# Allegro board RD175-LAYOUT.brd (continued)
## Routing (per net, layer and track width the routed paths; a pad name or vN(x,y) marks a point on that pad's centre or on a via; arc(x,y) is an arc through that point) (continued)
N552846: length 26.9
  TOP w0.7: v2(76.67,47.92) R71.1
  CONDUCTIVE3 w1: v2(76.67,47.92) 76.67,59.08 85.3,67.7 T5.10
N560018: length 3.2
  TOP w0.7: TP3.1 39.4,83.65
  BOTTOM w0.7: 39.1,83.35 R6.1
  BOTTOM w0.8: v2(39.12,83.35) 39.12,82.92
N560020: length 45.5
  TOP w0.6: 55.85,53.5 55.85,55.1 53.58,57.38 v1(47.5,57.38) ; v1(20.59,72.54) IC1.6 20.59,73.86
  CONDUCTIVE3 w0.6: v1(20.59,72.54) 20.59,72.39 35.6,57.38 v1(47.5,57.38)
N560028: length 2.2
  TOP w0.7: 33.75,47.2 Q1.1
N560032: length 7.4
  TOP w0.7: D6.2 76.9,44.2 76.67,43.98 C52.1 R72.2 82.47,43.2
N560040: length 3.8
  TOP w0.3: 88.58,50.2 R55.1 R56.2 ; IC3.8 88.62,50.2
N560044: length 52.7
  TOP w0.35: v2(98.45,52.62) 97.8,52.15 96.92,52.15
  CONDUCTIVE2 w1: v2(102.9,57.08) 103.85,58.02 103.85,71.3 104.25,71.7 104.25,80.75 103.9,81.1 103.9,84.8 101.65,87.05 v1(101.65,88.45) 101.65,89.45 103.62,91.42 v1(103.62,97.45)
  CONDUCTIVE3 w1: v2(98.45,52.62) v2(102.9,57.08)
  BOTTOM w0.7: v1(103.62,97.45) 102.72,97.45 ; R43.2 101.53,88.58 v1(101.65,88.45)
N560052: length 0.7
  TOP w0.6: 48.98,51.38 48.98,50.7
N560056: length 4.2
  CONDUCTIVE2 w0.6: v1(31.38,74.97) 31.38,73.95 TP6.1
  CONDUCTIVE3 w0.6: TP6.1 31.38,73.95 v1(31.38,74.97)
  BOTTOM w0.6: 31.43,73.92 31.38,73.97 v1(31.38,74.97) R13.1
N560060: length 4.2
  TOP w0.4: C121.2 49.65,21 50.1,21.45 50.52,21.45 ; C121.2 47.7,21 ; C121.2 48.98,19.85
N560066: length 25.4
  TOP w0.3: v1(89.92,49.5) 89.97,49.55 IC3.9 ; v1(78.55,37.67) R68.1
  CONDUCTIVE3 w0.3: v1(78.55,37.67) 86.8,37.67 89.92,40.8 v1(89.92,49.5)
N560076: length 1.2
  BOTTOM w0.7: v1(37.7,83.45) R6.2
N560080: length 31.9
  TOP w0.35: IC3.5 90.25,52.15 v2(89.58,52.67)
  CONDUCTIVE2 w0.6: v1(101.2,76.1) 101.1,76
  CONDUCTIVE2 w1: v2(98.03,61.12) 100.55,63.65 v1(100.55,66.38) 100.55,75.45 101.1,76
  BOTTOM w0.7: v1(101.2,76.1) R41.2 ; v1(100.55,66.38) R42.2
  BOTTOM w1: v2(98.03,61.12) v2(89.58,52.67)
N560082: length 2.7
  TOP w0.3: 96.92,53.45 96.92,53.48 97.64,53.48 97.96,53.8 R62.1
N560106: length 3.3
  TOP w0.7: Q7.3 C53.1 FB3.2
N560114: length 2.4
  TOP w0.3: C44.1 99.05,50.58 98.78,50.85 96.92,50.85
N560120: length 32.5
  TOP w0.6: TP23.1 62,55.62 62.35,55.27 D3.3 ; 43.95,74.14 v1(43.95,70.7)
  CONDUCTIVE3 w0.6: v1(43.95,70.7) 43.95,67.95 51.17,60.73 58.27,60.73 TP23.1
N560124: length 14.4
  TOP w0.3: R63.2 99.38,51.88 99,51.5 v1(98.12,51.5) 98.12,51.48 96.92,51.48 ; v1(98.95,42.17) C45.1
  CONDUCTIVE3 w0.3: v1(98.12,51.5) 99,51.5 99.67,50.83 99.67,47.05 98.95,46.33 v1(98.95,42.17)
N560134: length 27
  TOP w0.4: R27.1 R26.1 v1(59.4,42.42)
  TOP w0.5: v1(45.7,43.3) R21.1
  TOP w0.7: v1(45,46.5) 45,48.05 45.4,48.45 C11.1 R115.1
  CONDUCTIVE3 w0.6: 45.33,43.67 45,44 v1(45,46.5) ; 45.33,43.67 46.08,43.67 ; 45.33,43.67 v1(45.7,43.3) 46.08,43.67 ; 46.08,43.67 46.6,44.2 47.55,44.2 48.25,43.5 58.33,43.5 v1(59.4,42.42)
N560136: length 2
  TOP w0.3: 77.12,36.27 R68.2 75.08,36.27
N560152: length 14.6
  TOP w0.3: R64.1 TP26.1 ; 96.92,50.2 v1(98.12,50.2)
  CONDUCTIVE3 w0.3: TP26.1 93.4,42.4 95.42,44.42 95.42,47.5 v1(98.12,50.2)
N560170: length 1.4
  TOP w0.3: R52.2 R51.1
N560178: length 4.9
  TOP w0.3: C46.2 R65.1 R66.2 98.33,48.35 97.78,48.9 96.92,48.9
N560180: length 36.6
  TOP w0.4: IC122.5 59.92,19.65 ; v1(59.92,18.85) 59.92,17.98 59.77,17.82 ; IC123.2 62.38,22.68 62.8,23.1 C126.2 R128.2
  TOP w0.5: C124.1 60.25,19.75 61.05,20.55 61.83,20.55 62.38,21.1 IC123.2
  TOP w0.6: 53.12,21.43 C122.1 v1(53.12,19) ; v1(59.92,18.85) C124.1
  TOP w0.8: v2(56.33,31.15) C129.2 53.92,29.95
  CONDUCTIVE3 w0.8: v1(59.92,18.85) 56.23,18.85 56.08,19 v1(53.12,19) 53.12,23.5 54.6,24.98 54.6,29.43 v2(56.33,31.15)
N560194: length 2.5
  TOP w0.3: R57.2 91.12,47.58 91.12,48.88
N560198: length 1.9
  TOP w0.3: C13.2 IC2.12
N560204: length 38.9
  TOP w0.3: 49.5,44.2 C12.2 ; 49.5,44.2 IC2.16 ; 49.5,44.2 R22.1 R21.2 v1(47.1,43.3)
  TOP w0.5: v1(64.03,20.2) 64.92,20.2 ; 56.42,23.07 v1(57.62,23.07)
  CONDUCTIVE3 w0.3: v1(47.1,43.3) 47.1,42.6 57.62,32.08 v1(57.62,23.07) 60.5,20.2 v1(64.03,20.2)
N560212: length 1.3
  TOP w0.3: R67.2 R66.1
N560214: length 11.7
  TOP w0.3: R111.2 v1(42.88,4.45)
  BOTTOM w0.3: v1(53.33,5.1) 52.67,4.45 v1(42.88,4.45)
N560218: length 1.6
  TOP w0.4: D3.1 58.85,54.35 58.75,54.45
N560238: length 7.4
  TOP w0.25: C18.1 59.33,47.33 55.99,47.33
  TOP w0.4: R32.2 61.15,48 R31.2 C18.1 ; 55.99,47.33 IC2.4
N560240: length 2.4
  TOP w0.3: R58.2 98.33,49.27 98.05,49.55 96.92,49.55
N560246: length 1.9
  TOP w0.25: 55.99,46.67 56.38,46.67 56.5,46.55 R28.2
  TOP w0.4: IC2.3 55.99,46.67
N560250: length 1.2
  TOP w0.3: 78.47,45.77 R72.1
N560270: length 3
  TOP w0.25: 57.08,48.62 57.12,48.62 57.95,49.45 R29.2 ; 55.99,48.62 56.81,48.62
  TOP w0.4: IC2.6 55.99,48.62
  TOP w0.45: 56.81,48.62 C15.2
N560290: length 6.3
  TOP w0.4: 53.77,49.55 53.77,51.27 ; 53.77,49.55 53.55,49.77 53.55,51.05 53.77,51.27 ; 53.77,49.55 54.05,49.27 IC2.7 ; 53.77,51.27 53.77,51.83 54.1,52.15
N560306: length 36
  TOP w0.3: 64.87,36.25 R37.1 v1(51.05,36.25) ; IC2.13 48.3,47.33 v1(48.25,47.27) ; 64.88,36.26 64.9,36.28 IC4.4
  CONDUCTIVE3 w0.3: v1(51.05,36.25) 43.65,43.65 43.65,47.5 44.4,48.25 46.75,48.25 47.73,47.27 v1(48.25,47.27)
N560310:
  vias: v1(38.8,35.15) v1(38.8,34.3) v1(38.8,33.45) v1(38.8,32.6) v1(38.8,31.75) v1(38.8,30.9) v1(38.8,30.05) v1(38.8,29.2) v1(39.65,35.15) v1(39.65,34.3) v1(39.65,33.45) v1(39.65,32.6) v1(39.65,31.75) v1(39.65,30.9) v1(39.65,30.05) v1(39.65,29.2) v1(40.5,35.15) v1(40.5,34.3) v1(40.5,33.45) v1(40.5,32.6) v1(40.5,31.75) v1(40.5,30.9) v1(40.5,30.05) v1(40.5,29.2) v1(41.35,35.15) v1(41.35,34.3) v1(41.35,33.45) v1(41.35,32.6) v1(41.35,31.75) v1(41.35,30.9) v1(41.35,30.05) v1(41.35,29.2) v1(42.2,35.15) v1(42.2,34.3) v1(42.2,33.45) v1(42.2,32.6) v1(42.2,31.75) v1(42.2,30.9) v1(42.2,30.05) v1(42.2,29.2)
N560366: length 17.4
  BOTTOM w1.2: v2(20.57,80.66) 22.11,82.2 37.3,82.2
N560368: length 4.1
  TOP w0.25: 57.99,48.05 57.42,48.05 57.35,47.98 55.99,47.98
  TOP w0.3: R30.2 58.15,48.05
  TOP w0.4: IC2.5 55.99,47.98
  TOP w0.7: 58.15,48.05 R29.1 57.99,48.05
N560372: length 4.8
  TOP w0.3: IC3.1 92.12,54.75 92.85,55.48 R54.2 92.85,56.55 92.25,57.15 92.25,58
N560402: length 44.5
  TOP w0.3: v1(35.65,43.2) 35.65,47.2 ; CN2.1 42.55,23.68 38.9,20.02 31.75,20.02 J1.1
  CONDUCTIVE3 w0.3: v1(35.65,43.2) 34.42,41.98 34.42,30.27 40.7,24 CN2.1
N560442: length 3.4
  TOP w0.25: C17.2 56.62,45.65 56.25,46.02 55.99,46.02
  TOP w0.3: R27.2 C17.2
  TOP w0.4: 55.99,46.02 IC2.2
N560448: length 3.6
  TOP w0.7: 74.78,46.55 74.78,45.83 74.65,45.7 74.65,44.75 D6.1 74.65,44.65 74.65,43.38 74.85,43.17
N560522: length 5.5
  TOP w0.4: v1(60.35,51.6) D3.2 ; v1(60.35,49.4) R32.1 62.83,49.4
  CONDUCTIVE3 w0.4: v1(60.35,49.4) v1(60.35,51.6)
N560530: length 2.1
  TOP w0.25: 47.56,46.6 48.9,46.6 48.98,46.67 49.45,46.67
  TOP w0.7: 47.56,46.6 R23.2
N560660: length 0.7
  TOP w0.6: 55.83,50.67 R25.2
N560674: length 1.2
  TOP w0.3: R57.1 91.17,46.17
N560710: length 3.4
  TOP w0.4: 55.27,43.85 55.55,43.48 56.2,42.83 R26.2 ; IC2.1 C16.1
N560758: length 40.4
  TOP w0.6: 19.32,73.81 19.32,72.58 v1(19.27,72.54) ; 48.95,53.5 v1(48.95,54.4)
  CONDUCTIVE3 w0.6: v1(48.95,54.4) 47.85,55.5 35.02,55.5 18.98,71.55 18.98,72.24 v1(19.27,72.54)
N560892: length 2.7
  TOP w0.3: 96.92,54.75 97.8,54.75 98.15,55.1 R61.1
N568590: length 7.5
  TOP w0.3: IC122.6 58.48,20.98 57.9,21.55 R124.2 56.1,21.55 56.1,21.8 55.58,22.32 55.15,22.32 54.67,22.8 D122.2 54.6,23.07 53.92,22.4 53.15,22.4
N568875: length 2.8
  TOP w0.3: IC122.1 C123.2 R124.1
N570936: length 4.4
  TOP w0.3: TP31.1 57.08,17.8 R125.2 IC122.4
N571063: length 5.8
  TOP w0.3: R125.1 R126.1 R127.2 C125.2 IC123.4
N572220: length 6.8
  TOP w0.3: R131.2 R130.2 R129.2 R128.1 C126.1 ; 61.42,23.4 IC123.3
N572478: length 8.8
  TOP w0.4: 62.77,27.3 R130.1 63.7,27.3 TP32.1 65.25,23.82 64.92,23.5 D123.2 IC123.1
N585143: length 4
  TOP w0.3: IC10.3 R92.2 R91.2 C82.1
N585161: length 3
  TOP w0.3: IC10.4 82.15,31.25 R93.1
N585197: length 4
  TOP w0.3: IC9.1 75.24,27.25 75.67,27.25 75.88,27.05 C83.2 77.12,27.05
N585311: length 1.6
  TOP w0.3: 78.55,28.68 IC10.1 R94.2
N641223: length 3.4
  TOP w0.3: R131.1 63.45,28.68 IC9.4
N647990: length 1.4
  TOP w0.3: TP28.1 C45.2
N3802771: length 2.8
  TOP w0.3: 50.52,23.38 R133.2
N3805483: length 3.2
  TOP w0.3: IC11.9 46.14,6.84 R112.1 R111.1
N3805587: length 1.3
  TOP w0.3: IC11.10 46.64,6.05
N3805628: length 1.8
  TOP w0.3: IC11.11 47.14,6.46 R113.1
N3830864: length 1.4
  TOP w0.3: 53.92,26.2 53.92,27.55

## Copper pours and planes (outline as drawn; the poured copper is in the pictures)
I_11V on TOP: 61.47,9.8 61.43,9.81 61.4,9.83 60.98,10.25 60.96,10.28 60.95,10.32 60.95,11.38 60.96,11.42 60.98,11.45 61.2,11.67 61.23,11.69 61.27,11.7 62.53,11.7 62.57,11.69 62.6,11.67 62.82,11.45 62.84,11.42 62.85,11.38 62.85,10.32 62.84,10.28 62.82,10.25 62.4,9.83 62.37,9.81 62.33,9.8
I_11V on TOP: 26.12,78.33 26.08,78.33 26.05,78.35 25.88,78.52 25.86,78.55 25.85,78.59 25.85,80.25 25.88,80.32 25.95,80.35 26.53,80.35 26.57,80.34 26.6,80.32 26.67,80.25 26.69,80.22 26.7,80.18 26.7,78.64 26.69,78.6 26.67,78.57 26.45,78.35 26.42,78.33 26.38,78.33
IGND on TOP: 62.08,18.35 62,18.38 61.98,18.45 61.98,19.38 61.98,19.42 62,19.45 62.15,19.6 62.18,19.62 62.22,19.62 62.56,19.62 62.6,19.62 62.63,19.6 62.75,19.48 62.77,19.45 62.77,19.41 62.77,18.45 62.75,18.38 62.67,18.35
IGND on TOP: 67.5,57.31 67.54,57.12 68.05,56.55 68.16,56.38 68.2,56.19 68.2,52.81 68.16,52.62 68.06,52.46 67.65,52.05 67.54,51.88 67.5,51.69 67.5,9.5 67.5,9.47 67.5,1.67 67.47,1.51 66.99,1.03 66.83,1 10.14,1 10.1,1.01 10.07,1.03 9.83,1.27 9.81,1.3 9.8,1.34 9.8,4 8.1,8.1 4,9.8 1.34,9.8 1.3,9.81 1.27,9.83 1.03,10.07 1.01,10.1 1,10.14 1,104.26 1.01,104.3 1.03,104.33 1.27,104.57 1.3,104.59 1.34,104.6 4,104.6 8.1,106.3 9.8,110.4 9.8,113.06 9.81,113.1 9.83,113.13 10.07,113.37 10.1,113.39 10.14,113.4 66.83,113.4 66.99,113.37 67.12,113.28 67.47,112.89 67.5,112.73 ; 22 cut-outs
IGND on BOTTOM: 67.5,1.67 67.47,1.51 67.38,1.38 66.98,1.03 66.83,1 10.14,1 10.1,1.01 10.07,1.03 9.83,1.27 9.81,1.3 9.8,1.34 9.8,4 8.1,8.1 4,9.8 1.34,9.8 1.3,9.81 1.27,9.83 1.03,10.07 1.01,10.1 1,10.14 1,104.26 1.01,104.3 1.03,104.33 1.27,104.57 1.3,104.59 1.34,104.6 4,104.6 8.1,106.3 9.8,110.4 9.8,113.06 9.81,113.1 9.83,113.13 10.07,113.37 10.1,113.39 10.14,113.4 66.83,113.4 66.99,113.37 67.12,113.28 67.37,113.03 67.38,113.01 67.47,112.88 67.5,112.73 ; 55 cut-outs
IGND on CONDUCTIVE2: 67.5,1.67 67.47,1.51 67.38,1.38 66.99,1.03 66.83,1 10.14,1 10.1,1.01 10.07,1.03 9.83,1.27 9.81,1.3 9.8,1.34 9.8,4 8.1,8.1 4,9.8 1.34,9.8 1.3,9.81 1.27,9.83 1.03,10.07 1.01,10.1 1,10.14 1,104.26 1.01,104.3 1.03,104.33 1.27,104.57 1.3,104.59 1.34,104.6 4,104.6 8.1,106.3 9.8,110.4 9.8,113.06 9.81,113.1 9.83,113.13 10.07,113.37 10.1,113.39 10.14,113.4 66.83,113.4 66.99,113.37 67.12,113.28 67.38,113.02 67.47,112.89 67.5,112.73 ; 58 cut-outs
IGND on CONDUCTIVE3: 67.5,1.67 67.47,1.51 67.38,1.38 67.11,1.11 66.99,1.03 66.83,1 10.14,1 10.1,1.01 10.07,1.03 9.83,1.27 9.81,1.3 9.8,1.34 9.8,4 8.1,8.1 4,9.8 1.34,9.8 1.3,9.81 1.27,9.83 1.03,10.07 1.01,10.1 1,10.14 1,104.26 1.01,104.3 1.03,104.33 1.27,104.57 1.3,104.59 1.34,104.6 4,104.6 8.1,106.3 9.8,110.4 9.8,113.06 9.81,113.1 9.83,113.13 10.07,113.37 10.1,113.39 10.14,113.4 66.83,113.4 66.99,113.37 67.12,113.28 67.38,113.02 67.47,112.89 67.5,112.73 ; 36 cut-outs
Net_1 on BOTTOM: 130.6,-5.9 130.57,-5.97 130.5,-6 1.1,-6 1.03,-5.97 1,-5.9 1,-2.6 1.03,-2.53 1.1,-2.5 2.29,-2.5 3.32,-2.09 3.82,-1.03 3.89,-1 127.71,-1 127.78,-1.03 128.28,-2.09 129.31,-2.5 130.5,-2.5 130.57,-2.53 130.6,-2.6 ; 4 cut-outs
Net_2 on BOTTOM: 1,120.3 1.03,120.37 1.1,120.4 130.5,120.4 130.57,120.37 130.6,120.3 130.6,117 130.57,116.93 130.5,116.9 129.31,116.9 128.28,116.49 127.78,115.43 127.71,115.4 3.89,115.4 3.82,115.43 3.32,116.49 2.29,116.9 1.1,116.9 1.03,116.93 1,117 ; 4 cut-outs
Net_3 on CONDUCTIVE3: 130.6,-5.9 130.57,-5.97 130.5,-6 1.1,-6 1.03,-5.97 1,-5.9 1,-2.6 1.03,-2.53 1.1,-2.5 2.29,-2.5 3.32,-2.09 3.82,-1.03 3.89,-1 127.71,-1 127.78,-1.03 128.28,-2.09 129.31,-2.5 130.5,-2.5 130.57,-2.53 130.6,-2.6 ; 2 cut-outs
Net_4 on CONDUCTIVE3: 1,120.3 1.03,120.37 1.1,120.4 130.5,120.4 130.57,120.37 130.6,120.3 130.6,117 130.57,116.93 130.5,116.9 129.31,116.9 128.28,116.49 127.78,115.43 127.71,115.4 3.89,115.4 3.82,115.43 3.32,116.49 2.29,116.9 1.1,116.9 1.03,116.93 1,117 ; 2 cut-outs
Net_5 on CONDUCTIVE2: 130.6,-5.9 130.57,-5.97 130.5,-6 1.1,-6 1.03,-5.97 1,-5.9 1,-2.6 1.03,-2.53 1.1,-2.5 2.29,-2.5 3.32,-2.09 3.82,-1.03 3.89,-1 127.71,-1 127.78,-1.03 128.28,-2.09 129.31,-2.5 130.5,-2.5 130.57,-2.53 130.6,-2.6 ; 2 cut-outs
Net_6 on CONDUCTIVE2: 1,120.3 1.03,120.37 1.1,120.4 130.5,120.4 130.57,120.37 130.6,120.3 130.6,117 130.57,116.93 130.5,116.9 129.31,116.9 128.28,116.49 127.78,115.43 127.71,115.4 3.89,115.4 3.82,115.43 3.32,116.49 2.29,116.9 1.1,116.9 1.03,116.93 1,117 ; 2 cut-outs
Net_7 on TOP: 130.6,-5.9 130.57,-5.97 130.5,-6 1.1,-6 1.03,-5.97 1,-5.9 1,-2.6 1.03,-2.53 1.1,-2.5 2.29,-2.5 3.32,-2.09 3.82,-1.03 3.89,-1 127.71,-1 127.78,-1.03 128.28,-2.09 129.31,-2.5 130.5,-2.5 130.57,-2.53 130.6,-2.6 ; 4 cut-outs
Net_8 on TOP: 1,120.3 1.03,120.37 1.1,120.4 130.5,120.4 130.57,120.37 130.6,120.3 130.6,117 130.57,116.93 130.5,116.9 129.31,116.9 128.28,116.49 127.78,115.43 127.71,115.4 3.89,115.4 3.82,115.43 3.32,116.49 2.29,116.9 1.1,116.9 1.03,116.93 1,117 ; 4 cut-outs
OGND on TOP: 72.5,51.69 72.46,51.88 72.35,52.05 71.95,52.45 71.84,52.62 71.8,52.81 71.8,56.19 71.84,56.38 71.95,56.55 72.46,57.12 72.5,57.31 72.5,112.73 72.53,112.89 72.88,113.28 73.01,113.37 73.17,113.4 121.46,113.4 121.5,113.39 121.53,113.37 121.77,113.13 121.79,113.1 121.8,113.06 121.8,110.4 123.5,106.3 127.6,104.6 130.26,104.6 130.3,104.59 130.33,104.57 130.57,104.33 130.59,104.3 130.6,104.26 130.6,102.9 130.6,102.9 130.6,93.25 130.6,10.14 130.59,10.1 130.57,10.07 130.33,9.83 130.3,9.81 130.26,9.8 127.6,9.8 123.5,8.1 121.8,4 121.8,1.34 121.79,1.3 121.77,1.27 121.53,1.03 121.5,1.01 121.46,1 73.17,1 73.01,1.03 72.88,1.12 72.62,1.38 72.53,1.51 72.5,1.67 ; 22 cut-outs
OGND on BOTTOM: 85.6,45.15 85.56,45.16 85.53,45.18 80.3,50.4 80.28,50.44 80.28,50.48 80.28,52.42 80.28,52.46 80.3,52.5 81.91,54.09 81.95,54.1 86.09,54.1 86.17,54.12 86.23,54.16 86.44,54.37 86.48,54.43 86.5,54.51 86.5,57.71 86.51,57.75 86.53,57.78 88.6,59.85 88.63,59.87 88.67,59.88 90.96,59.88 91,59.87 91.03,59.85 91.22,59.65 91.25,59.62 91.79,59.08 91.91,59 92.04,58.98 93.53,58.98 93.58,58.96 93.62,58.92 93.79,58.7 94.03,58.56 94.08,58.52 94.1,58.47 94.1,58.3 94.09,58.26 94.07,58.23 89.04,53.21 89.04,52.14 90.11,52.14 93.63,55.67 93.66,55.69 93.7,55.7 102.28,55.7 102.31,55.69 102.35,55.67 103.02,55 103.04,54.96 103.05,54.92 103.05,45.23 103.04,45.19 103.02,45.15 102.2,44.33 102.16,44.31 102.12,44.3 88.17,44.3 88.13,44.31 88.1,44.33 87.9,44.52 87.88,44.55 87.88,44.59 87.88,45.3 86.83,46.35 85.78,45.3 85.78,45.25 85.75,45.18 85.68,45.15 ; 6 cut-outs
OGND on BOTTOM: 72.5,112.73 72.53,112.89 72.89,113.29 73.01,113.37 73.17,113.4 121.46,113.4 121.5,113.39 121.53,113.37 121.77,113.13 121.79,113.1 121.8,113.06 121.8,110.4 123.5,106.3 127.6,104.6 130.26,104.6 130.3,104.59 130.33,104.57 130.57,104.33 130.59,104.3 130.6,104.26 130.6,10.14 130.59,10.1 130.57,10.07 130.33,9.83 130.3,9.81 130.26,9.8 127.6,9.8 123.5,8.1 121.8,4 121.8,1.34 121.79,1.3 121.77,1.27 121.53,1.03 121.5,1.01 121.46,1 73.17,1 73.01,1.03 72.62,1.38 72.53,1.51 72.5,1.67 ; 26 cut-outs
OGND on CONDUCTIVE2: outline of 90 points within 80.28,44.3 103.05,59.88 ; 6 cut-outs
OGND on CONDUCTIVE2: 72.5,112.73 72.53,112.89 72.62,113.02 72.88,113.28 73.01,113.37 73.17,113.4 121.46,113.4 121.5,113.39 121.53,113.37 121.77,113.13 121.79,113.1 121.8,113.06 121.8,110.4 123.5,106.3 127.6,104.6 130.26,104.6 130.3,104.59 130.33,104.57 130.57,104.33 130.59,104.3 130.6,104.26 130.6,10.14 130.59,10.1 130.57,10.07 130.33,9.83 130.3,9.81 130.26,9.8 127.6,9.8 123.5,8.1 121.8,4 121.8,1.34 121.79,1.3 121.77,1.27 121.53,1.03 121.5,1.01 121.46,1 73.17,1 73.01,1.03 72.62,1.38 72.53,1.51 72.5,1.67 ; 34 cut-outs
OGND on CONDUCTIVE3: 99.59,44.3 99.55,44.31 99.52,44.33 99.38,44.47 99.36,44.5 99.35,44.54 99.35,46.12 99.36,46.16 99.38,46.19 99.96,46.77 100.04,46.9 100.08,47.05 100.08,50.83 100.04,50.98 99.96,51.11 99.28,51.78 99.24,51.82 99.21,51.86 99.2,51.9 99.2,52.27 99.21,52.31 99.23,52.34 102.28,55.4 102.31,55.42 102.35,55.42 102.55,55.42 102.59,55.42 103.02,55 103.04,54.96 103.05,54.93 103.05,45.23 103.04,45.19 103.02,45.15 102.79,44.93 102.2,44.33 102.16,44.31 102.13,44.3 101.87,44.3 101.83,44.31 101.8,44.33 101.6,44.52 101.58,44.55 101.58,44.59 101.58,45.05 101.58,45.08 100.92,46.02 100.27,45.08 100.28,45.05 100.28,44.54 100.27,44.5 100.25,44.47 100.1,44.33 100.07,44.31 100.03,44.3
OGND on CONDUCTIVE3: 72.5,112.73 72.53,112.89 72.62,113.02 72.88,113.28 73.01,113.37 73.17,113.4 121.46,113.4 121.5,113.39 121.53,113.37 121.77,113.13 121.79,113.1 121.8,113.06 121.8,110.4 123.5,106.3 127.6,104.6 130.26,104.6 130.3,104.59 130.33,104.57 130.57,104.33 130.59,104.3 130.6,104.26 130.6,10.14 130.59,10.1 130.57,10.07 130.33,9.83 130.3,9.81 130.26,9.8 127.6,9.8 123.5,8.1 121.8,4 121.8,1.34 121.79,1.3 121.77,1.27 121.53,1.03 121.5,1.01 121.46,1 73.17,1 73.01,1.03 72.89,1.11 72.62,1.38 72.53,1.51 72.5,1.67 ; 32 cut-outs
OGND on CONDUCTIVE3: outline of 164 points within 80.28,44.3 100.05,59.88 ; 2 cut-outs
N551939 on TOP: 98.15,107.07 98.2,106.82 98.34,106.61 98.56,106.39 98.77,106.25 99.02,106.2 116.32,106.2 116.36,106.19 116.39,106.17 126.52,96.04 126.54,96.01 126.55,95.97 126.55,89.47 126.54,89.43 126.52,89.4 126.33,89.2 126.3,89.18 126.26,89.17 125.88,89.17 125.78,89.15 125.74,89.12 125.63,89.01 125.58,88.92 125.58,88.87 125.58,86.52 125.55,86.45 125.48,86.42 113.17,86.42 113.1,86.45 113.08,86.52 113.08,88.87 113.06,88.94 113.02,89.01 112.91,89.12 112.84,89.16 112.77,89.17 110.51,89.17 110.46,89.19 110.42,89.23 110.37,89.32 110.3,89.4 110.1,89.59 109.88,89.75 109.61,89.8 100.67,89.8 100.44,89.75 100.25,89.62 99.48,88.85 99.45,88.83 99.41,88.83 95.44,88.83 95.17,88.77 94.95,88.62 94.33,88 94.3,87.98 94.26,87.97 89.06,87.97 88.99,88 88.96,88.05 88.3,88.97 87.2,89.17 87.15,89.17 87.1,89.2 86.48,89.82 86.46,89.85 86.45,89.89 86.45,104.91 86.46,104.95 86.48,104.98 91.97,110.47 92,110.49 92.04,110.5 98.05,110.5 98.12,110.47 98.15,110.4 ; 4 cut-outs
N551939 on BOTTOM: 88.75,88.6 88.71,88.61 88.67,88.64 88.01,89.11 87.2,89.17 87.15,89.17 87.1,89.2 86.48,89.82 86.46,89.85 86.45,89.89 86.45,104.91 86.46,104.95 86.48,104.98 91.97,110.47 92,110.49 92.04,110.5 98.05,110.5 98.12,110.47 98.15,110.4 98.15,89.55 98.14,89.51 98.12,89.48 97.84,89.19 97.81,89.17 97.77,89.17 91.4,89.17 91.03,89.05 90.81,88.73 90.76,88.65 90.72,88.61 90.67,88.6
N551939 on CONDUCTIVE2, CONDUCTIVE3: 94.64,91.92 94.6,91.93 94.57,91.95 94.48,92.05 94.46,92.08 94.45,92.12 94.45,96.18 94.46,96.22 94.48,96.25 94.57,96.35 94.6,96.37 94.64,96.38 97.91,96.38 97.95,96.37 97.98,96.35 98.12,96.2 98.14,96.17 98.15,96.13 98.15,92.17 98.14,92.13 98.12,92.1 97.98,91.95 97.95,91.93 97.91,91.92
N551939 on CONDUCTIVE2, CONDUCTIVE3: 93.75,106.55 93.71,106.55 93.67,106.58 93.58,106.67 93.56,106.7 93.55,106.74 93.55,110.01 93.56,110.05 93.58,110.08 93.67,110.17 93.7,110.19 93.74,110.2 97.81,110.2 97.85,110.19 97.88,110.17 97.97,110.08 97.99,110.05 98,110.01 98,106.74 97.99,106.7 97.97,106.67 97.88,106.58 97.84,106.55 97.8,106.55
N551939 on CONDUCTIVE2, CONDUCTIVE3: 88.04,90.92 88,90.93 87.97,90.95 86.63,92.3 86.61,92.33 86.6,92.37 86.6,98.21 86.61,98.25 86.63,98.28 88.4,100.05 88.43,100.07 88.47,100.08 91.58,100.08 91.62,100.07 91.65,100.05 91.8,99.9 91.82,99.87 91.83,99.83 91.83,91.17 91.82,91.13 91.8,91.1 91.65,90.95 91.62,90.93 91.58,90.92
N552199 on CONDUCTIVE3 (solid shape): 94.91,32.76 94.68,33.04 94.96,33.26 96.11,33.15 96.26,33.08 96.33,32.93 96.44,31.78 96.44,31.75 96.37,31.58 96.19,31.5 96.03,31.57 95.94,31.73 95.93,31.93 95.11,32.75
N552199 on TOP: 95.24,21 95.2,21.01 95.17,21.03 93.18,23.02 93.16,23.05 93.15,23.09 93.15,32.51 93.16,32.55 93.18,32.58 96.57,35.97 96.6,35.99 96.64,36 108.47,36 108.57,36.03 108.61,36.06 111.49,38.94 111.53,39.01 111.55,39.08 111.55,71.13 111.56,71.17 111.58,71.2 111.77,71.4 111.8,71.42 111.84,71.42 112.72,71.42 112.79,71.44 112.86,71.48 113.02,71.64 113.06,71.71 113.08,71.78 113.08,74.08 113.1,74.15 113.17,74.17 125.47,74.17 125.55,74.15 125.58,74.08 125.58,71.78 125.59,71.71 125.63,71.64 125.72,71.55 125.79,71.51 125.87,71.49 126.19,71.49 126.23,71.48 126.26,71.46 126.52,71.2 126.54,71.17 126.55,71.13 126.55,32.82 126.54,32.78 126.52,32.75 114.8,21.03 114.77,21.01 114.73,21
N552199 on BOTTOM, CONDUCTIVE2, CONDUCTIVE3: 93.39,24.8 93.35,24.81 93.32,24.83 93.18,24.97 93.16,25 93.15,25.04 93.15,31.61 93.16,31.65 93.18,31.68 94.27,32.77 94.3,32.79 94.34,32.8 95.91,32.8 95.95,32.79 95.98,32.77 99.72,29.03 99.74,29 99.75,28.96 99.75,25.09 99.74,25.05 99.72,25.02 99.53,24.83 99.5,24.81 99.46,24.8
N552352 on TOP: outline of 100 points within 2.8,40.1 53.75,101.75
N552352 on BOTTOM: 42.45,94.35 42.38,94.38 42.35,94.45 42.35,96.62 42.38,96.7 42.45,96.72 43.55,96.72 43.62,96.7 43.65,96.62 43.65,94.45 43.62,94.38 43.55,94.35
N552352 on BOTTOM, CONDUCTIVE2, CONDUCTIVE3: 47.47,91.47 47.43,91.48 47.4,91.5 47.1,91.8 47.08,91.83 47.08,91.87 47.08,98.46 47.08,98.5 47.1,98.53 47.42,98.85 47.45,98.87 47.49,98.88 53.11,98.88 53.15,98.87 53.18,98.85 53.72,98.3 53.74,98.27 53.75,98.23 53.75,92.14 53.74,92.1 53.72,92.07 53.15,91.5 53.12,91.48 53.08,91.47
N552464 on TOP: 101.7,86.05 101.67,85.98 101.6,85.95 100.9,85.95 100.78,85.93 100.69,85.86 99.64,84.82 99.62,84.8 99.58,84.79 98.94,84.46 98.61,83.81 98.6,83.78 98.58,83.76 98.18,83.35 98.02,83.08 98,82.93 98,67.27 98,67.24 97.96,67.14 97.94,67.06 97.68,66.64 97.22,66.47 92.72,66.47 92.68,66.48 92.65,66.5 89.03,70.12 89.01,70.15 89,70.19 89,72.72 88.88,73.3 88.55,73.79 86.59,75.73 86.43,75.9 86.42,75.94 86.42,85.48 86.44,85.53 86.45,85.55 87.1,86.2 87.15,86.23 87.2,86.23 88.28,86.42 88.95,87.3 88.98,87.35 89.04,87.38 94.3,87.38 94.53,87.42 94.73,87.55 95.37,88.2 95.4,88.22 95.44,88.22 99.46,88.22 99.5,88.22 99.53,88.2 100.17,87.56 100.4,87.4 100.67,87.35 101.6,87.35 101.67,87.32 101.7,87.25 ; 1 cut-out
N552464 on CONDUCTIVE2: 94.49,78.22 94.45,78.23 94.42,78.25 94.33,78.35 94.31,78.38 94.3,78.42 94.3,83.76 94.33,83.83 94.4,83.86 95.1,83.86 95.17,83.83 95.2,83.76 95.2,83.1 95.22,82.98 95.29,82.89 95.41,82.76 95.51,82.7 95.62,82.67 97.76,82.67 97.8,82.67 97.83,82.65 97.97,82.5 97.99,82.47 98,82.43 98,78.34 97.99,78.3 97.97,78.27 97.95,78.25 97.92,78.23 97.88,78.22
N552464 on CONDUCTIVE2, CONDUCTIVE3: 88.04,75.92 88,75.93 87.97,75.95 86.63,77.3 86.61,77.33 86.6,77.37 86.6,83.21 86.61,83.25 86.63,83.28 88.4,85.05 88.43,85.07 88.47,85.08 91.58,85.08 91.62,85.07 91.65,85.05 91.8,84.9 91.82,84.87 91.83,84.83 91.83,76.17 91.82,76.13 91.8,76.1 91.65,75.95 91.62,75.93 91.58,75.92
N552464 on CONDUCTIVE2, CONDUCTIVE3: 94.49,70.1 94.45,70.11 94.42,70.13 94.33,70.22 94.31,70.25 94.3,70.29 94.3,74.36 94.31,74.4 94.33,74.43 94.42,74.52 94.45,74.54 94.49,74.55 97.76,74.55 97.8,74.54 97.83,74.52 97.97,74.38 97.99,74.35 98,74.31 98,70.34 97.99,70.3 97.97,70.27 97.83,70.13 97.8,70.11 97.76,70.1
N560012 on BOTTOM: 101.92,77.15 101.85,77.18 101.83,77.25 101.83,77.78 101.78,77.93 101.74,77.99 101.69,78.03 101.56,78.11 101.48,78.12 98.8,78.12 98.73,78.15 98.7,78.22 98.7,78.87 98.73,78.94 98.8,78.97 100.8,78.97 100.9,79.07 100.93,79.09 100.97,79.1 102.47,79.1 102.55,79.07 102.58,79 102.58,78.1 102.6,78.05 102.62,78.02 102.62,77.98 102.62,77.25 102.6,77.18 102.53,77.15
N560018 on TOP: 38.97,82.95 38.93,82.96 38.9,82.98 38.75,83.12 38.73,83.15 38.73,83.19 38.73,84.3 38.75,84.37 38.83,84.4 39.16,84.4 39.2,84.39 39.23,84.37 39.8,83.8 39.82,83.77 39.83,83.73 39.83,83.44 39.82,83.4 39.8,83.37 39.4,82.98 39.37,82.96 39.33,82.95
N560018 on BOTTOM: 38.8,82.17 38.73,82.2 38.7,82.28 38.7,82.97 38.73,83.05 38.8,83.08 39.42,83.08 39.5,83.05 39.52,82.97 39.52,82.72 39.52,82.68 39.5,82.65 39.05,82.2 39.02,82.18 38.98,82.17
N560054 on TOP: 32.19,40.25 32.15,40.26 32.12,40.28 31.28,41.12 31.26,41.15 31.25,41.19 31.25,42.25 31.28,42.32 31.35,42.35 33.05,42.35 33.19,42.29 33.25,42.15 33.25,42.03 33.28,41.93 33.31,41.89 33.84,41.36 33.93,41.31 33.98,41.3 34.8,41.3 34.87,41.27 34.9,41.2 34.9,40.6 34.87,40.53 34.8,40.5 33.98,40.5 33.88,40.47 33.84,40.44 33.68,40.28 33.65,40.26 33.61,40.25
N560076 on TOP: outline of 102 points within 16.77,74.33 40.75,84.4
N560216 on TOP: 25.24,71.46 25.2,71.47 25.17,71.49 24.95,71.71 24.93,71.74 24.93,71.78 24.93,72.34 24.93,72.38 24.95,72.42 25.17,72.63 25.2,72.65 25.24,72.66 26.61,72.66 26.65,72.65 26.68,72.63 26.8,72.52 26.82,72.48 26.82,72.44 26.82,71.68 26.82,71.64 26.8,71.61 26.68,71.49 26.65,71.47 26.61,71.46
N560290 on TOP: 53.65,51 53.58,51.03 53.55,51.1 53.55,54.55 53.58,54.62 53.65,54.65 54.19,54.65 54.23,54.64 54.26,54.62 54.62,54.26 54.64,54.23 54.65,54.19 54.65,51.1 54.62,51.03 54.55,51
N560310 on TOP: 16.54,21.45 16.5,21.46 16.47,21.48 14.53,23.42 14.51,23.45 14.5,23.49 14.5,38.8 14.53,38.87 14.6,38.9 15.6,38.9 15.67,38.87 15.7,38.8 15.7,33.68 15.72,33.61 15.76,33.54 15.89,33.41 15.96,33.37 16.03,33.35 17.65,33.35 17.76,33.39 17.8,33.5 17.8,34.5 17.83,34.57 17.9,34.6 25.6,34.6 25.67,34.57 25.7,34.5 25.7,33.5 25.74,33.39 25.85,33.35 27.17,33.35 27.24,33.37 27.31,33.41 27.39,33.49 27.43,33.56 27.45,33.63 27.45,35.21 27.46,35.25 27.48,35.28 27.67,35.47 27.7,35.49 27.74,35.5 42.58,35.5 42.62,35.49 42.65,35.47 45.22,32.9 45.24,32.87 45.25,32.83 45.25,28.39 45.24,28.35 45.22,28.32 38.38,21.48 38.35,21.46 38.31,21.45
N560366 on BOTTOM: 37.2,81.6 37.13,81.63 37.1,81.7 37.1,82.7 37.13,82.77 37.2,82.8 37.78,82.8 37.82,82.79 37.85,82.77 37.97,82.65 37.99,82.62 38,82.58 38,81.82 37.99,81.78 37.97,81.75 37.85,81.63 37.82,81.61 37.78,81.6
N560656 on TOP: 25.24,69.56 25.2,69.57 25.17,69.59 24.95,69.81 24.93,69.84 24.93,69.88 24.93,70.44 24.93,70.48 24.95,70.52 25.17,70.73 25.2,70.75 25.24,70.76 26.61,70.76 26.65,70.75 26.68,70.73 26.8,70.62 26.82,70.58 26.82,70.55 26.82,69.78 26.82,69.74 26.8,69.71 26.68,69.59 26.65,69.57 26.61,69.56
N642654 on TOP: 105.6,83.6 105.53,83.63 105.5,83.7 105.5,85.2 104.75,85.95 103.7,85.95 103.63,85.98 103.6,86.05 103.6,87.31 103.61,87.35 103.63,87.38 104.12,87.87 104.15,87.89 104.19,87.9 106.8,87.9 106.87,87.87 106.9,87.8 106.9,83.82 106.89,83.78 106.87,83.75 106.85,83.72 106.85,83.7 106.82,83.63 106.75,83.6
N3799991 on TOP: 105.74,66.7 105.7,66.71 105.67,66.73 105.39,67.01 105.37,67.04 105.36,67.08 105.36,76.45 105.39,76.52 105.47,76.55 106.76,76.55 106.8,76.54 106.83,76.52 106.92,76.43 106.94,76.4 106.95,76.36 106.95,67.19 106.94,67.15 106.92,67.12 106.53,66.73 106.5,66.71 106.46,66.7
N3800429 on BOTTOM: 105.98,103.86 105.94,103.87 105.91,103.89 105.61,104.19 105.59,104.22 105.58,104.26 105.58,104.94 105.59,104.98 105.61,105.01 106.03,105.42 106.06,105.44 106.1,105.45 113.76,105.45 113.8,105.44 113.83,105.42 113.9,105.35 113.92,105.32 113.92,105.28 113.92,103.97 113.9,103.89 113.83,103.86
N3804695 on TOP: 48.59,11.1 48.51,11.13 48.48,11.2 48.48,12.59 48.49,12.63 48.51,12.66 48.87,13.02 48.9,13.04 48.94,13.05 50.25,13.05 50.35,13.08 50.42,13.15 50.45,13.25 50.45,14.05 50.48,14.12 50.55,14.15 51.43,14.15 51.47,14.14 51.5,14.12 51.72,13.9 51.74,13.87 51.75,13.83 51.75,12.25 51.72,12.18 51.65,12.15 50.42,12.15 50.38,12.16 50.35,12.18 50.28,12.25 50.19,12.3 50.14,12.3 49.18,12.3 49.08,12.28 49.04,12.25 48.84,12.05 48.79,11.96 48.78,11.91 48.78,11.2 48.76,11.13 48.69,11.1

Small or netless copper shapes (teardrops, artwork), in the pictures only: 35 on TOP, 5 on CONDUCTIVE3, 9 on BOTTOM, 2 on CONDUCTIVE2

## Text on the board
Ref Des/Silkscreen Bottom: R5 | R6 | CN1 | CN2 | CN3 | R48 | TP11 | TP8 | CN5 | CN4 | TP9 | R43 | R44 | TP12 | C32 | C33 | D13 | TP101 | TP131 | R102 | R101 | R103 | TP102 | TP132 | R104 | R47 | R13 | C8 | Q8 | Q9 | Q10 | Q11 | D | R42 | 1 | S | G | R41 | R105 | ENABLE | GND IN | DC IN | 24V OUT | GND OUT
Ref Des/Silkscreen Top: IC1 | 4 | 5 | C5 | 8 | 1 | C2 | R10 | R117 | TP71 | TP72 | R12 | TP42 | R11 | 2 | TP6 | J1 | R2 | TP41 | Q1 | R9 | C1 | TP2 | TP5 | Q2 | C3 | R3 | FB1 | C9 | TP21 | 6 | R15 | TP3 | C11 | IC11 | R21 | C13 | 9 | 3 | T2 | R23 | R134 | 7 | R114 | C14 | R124 | C122 | IC124 | TP31 | R116 | C128 | C16 | D122 | R26 | R129 | TP23 | R128 | C126 | R27 | R131 | R130 | T5 | TP22 | IC123 | C125 | R127 | R28 | C17 | TP32 | IC4 | IC9 | C61 | D6 | R71 | R94 | C53 | IC10 | TP25 | C82 | FB3 | R92 | R91 | R52 | TP27 | TP24 | 16 | R64 | C42 | TP26 | R53 | C43 | R67 | TP28 | C45 | R54 | R66 | R61 | C65 | C66 | R63 | R65 | C46 | R62 | D11 | C44 | R58 | C36 | C31 | C34 | C35 | R1 | D2 | C6 | L1 | Q3 | C10 | R16 | C7 | R111 | R112 | R122 | R115 | C112 | C121 | R24 | R113 | R121 | R22 | R133 | IC121 | C123 | C12 | IC2 | C113 | C111 | R25 | IC122 | C129 | R125 | R33 | C124 | R126 | L101 | D3 | R37 | FB2 | C15 | R29 | D123 | R30 | C18 | R32 | R31 | R34 | D5 | C83 | C81 | C52 | R72 | R68 | D8 | C64 | R93 | Q7 | D12 | R55 | R56 | C41 | R51 | R57 | C67 | IC3 | 20 | 11 | C49 | R46 | D10 | L2 | S | G | D | (ON:SHORT) | REMOTE | IGND | ENABLE | GND IN | DC IN | CURRENT | I 11V | SENSE | O 10V | OGND | /PGOOD | 24V OUT | GND OUT
